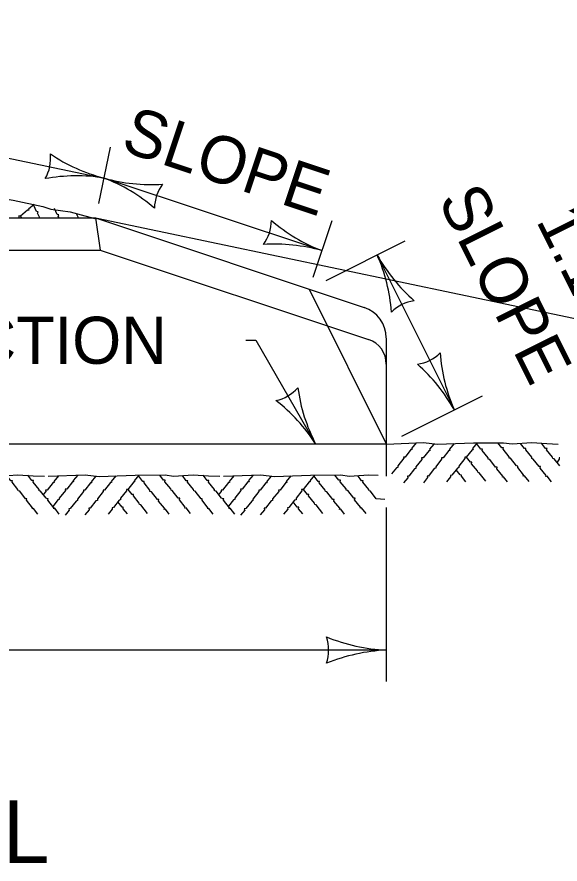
# Model space of a CAD drawing. Extents: x 49991.4 to 50021, y 49987.6 to 50011.4.
# Drawn here: x 50014.7 to 50015.391, y 49996.72 to 49997.798 of the extents above; entities that cross this region are included whole.
import ezdxf

# ---------------------------------------------------------------- set-up
doc = ezdxf.new("R2010")
doc.units = 0
for name, color, linetype in [('Level 1', 7, 'Continuous'), ('Level 2', 7, 'Continuous'), ('Level 3', 7, 'Continuous'), ('Level 4', 7, 'Continuous')]:
    doc.layers.add(name, color=color, linetype=linetype)

msp = doc.modelspace()

# ---------------------------------------------------------------- linework, layer by layer
at = {"layer": 'Level 1'}
for p, q in [((50012.6493, 49997.5423), (50014.7997, 49997.5423)), ((50014.7997, 49997.5423), (50015.1415, 49997.4284)), ((50015.1696, 49997.3894), (50015.1696, 49997.2136))]:
    msp.add_line(p, q, dxfattribs=at)
for points in [[(50014.5862, 49997.5861), (50014.6327, 49997.5783), (50014.6498, 49997.5726), (50014.6948, 49997.5648), (50014.7326, 49997.557), (50014.7427, 49997.5534), (50014.7674, 49997.5501), (50014.786, 49997.5449), (50014.8003, 49997.5411)], [(50014.7215, 49997.5594), (50014.7143, 49997.5536), (50014.7146, 49997.5521), (50014.7131, 49997.5524), (50014.704, 49997.5446), (50014.7022, 49997.545), (50014.7019, 49997.5423)], [(50014.7289, 49997.5423), (50014.7257, 49997.5486), (50014.7264, 49997.5503), (50014.7246, 49997.5506), (50014.721, 49997.5581)], [(50014.7532, 49997.5423), (50014.752, 49997.5446), (50014.7527, 49997.5464), (50014.7509, 49997.5467), (50014.7473, 49997.5542)], [(50014.7054, 49997.5423), (50014.7044, 49997.5444)], [(50014.7779, 49997.5423), (50014.7755, 49997.5476)], [(50015.1698, 49997.2545), (50015.217, 49997.2564), (50015.2349, 49997.2545), (50015.2805, 49997.256), (50015.3189, 49997.2562), (50015.3296, 49997.2548), (50015.3546, 49997.2564), (50015.3738, 49997.2554), (50015.3885, 49997.2545)], [(50015.2078, 49997.2562), (50015.2018, 49997.249), (50015.2025, 49997.2474), (50015.201, 49997.2474), (50015.1936, 49997.238), (50015.1916, 49997.238), (50015.192, 49997.2364), (50015.1842, 49997.2268), (50015.1842, 49997.2248), (50015.1826, 49997.2244), (50015.1764, 49997.2164)], [(50015.2302, 49997.2544), (50015.2247, 49997.2478), (50015.2256, 49997.2462), (50015.2241, 49997.2462), (50015.2166, 49997.2368), (50015.2146, 49997.2368), (50015.2148, 49997.235), (50015.2072, 49997.2254), (50015.2072, 49997.2234), (50015.2056, 49997.223), (50015.1982, 49997.2134), (50015.1965, 49997.2134), (50015.1968, 49997.2114), (50015.1916, 49997.2052)], [(50015.2559, 49997.2552), (50015.2499, 49997.2479), (50015.2506, 49997.2464), (50015.2492, 49997.2464), (50015.2418, 49997.237), (50015.2397, 49997.237), (50015.24, 49997.2352), (50015.2325, 49997.2256), (50015.2325, 49997.2239), (50015.2307, 49997.2232), (50015.2235, 49997.2138), (50015.2216, 49997.2136), (50015.222, 49997.2119), (50015.2168, 49997.2053)], [(50015.2853, 49997.256), (50015.2793, 49997.2488), (50015.28, 49997.2473), (50015.2787, 49997.2473), (50015.2712, 49997.238), (50015.2694, 49997.238), (50015.2696, 49997.236), (50015.2619, 49997.2264), (50015.2619, 49997.2248), (50015.2602, 49997.224), (50015.2529, 49997.2148), (50015.2512, 49997.2144), (50015.2514, 49997.2128), (50015.2463, 49997.2064)], [(50015.3237, 49997.2064), (50015.3189, 49997.2126), (50015.3174, 49997.2124), (50015.3177, 49997.2138), (50015.3102, 49997.223), (50015.3106, 49997.225), (50015.3087, 49997.225), (50015.3012, 49997.2348), (50015.2994, 49997.2352), (50015.2992, 49997.2368), (50015.2918, 49997.2462), (50015.2919, 49997.2479), (50015.2901, 49997.248), (50015.285, 49997.2546)], [(50015.3512, 49997.2068), (50015.3456, 49997.2142), (50015.3438, 49997.2138), (50015.3442, 49997.2154), (50015.3368, 49997.2246), (50015.337, 49997.2264), (50015.3354, 49997.2268), (50015.3278, 49997.2364), (50015.3261, 49997.2366), (50015.3258, 49997.2384), (50015.3182, 49997.2478), (50015.3186, 49997.2496), (50015.3166, 49997.2496), (50015.3116, 49997.2562)], [(50015.3798, 49997.2064), (50015.3742, 49997.2134), (50015.3728, 49997.2132), (50015.373, 49997.2144), (50015.3656, 49997.2239), (50015.366, 49997.2258), (50015.364, 49997.226), (50015.3566, 49997.2354), (50015.3548, 49997.2359), (50015.3546, 49997.2378), (50015.3471, 49997.247), (50015.3472, 49997.2488), (50015.3456, 49997.2488), (50015.3405, 49997.2554)], [(50015.3903, 49997.2268), (50015.3832, 49997.2358), (50015.3816, 49997.236), (50015.3813, 49997.2378), (50015.3736, 49997.2472), (50015.3741, 49997.249), (50015.3722, 49997.249), (50015.3669, 49997.2558)], [(50015.2962, 49997.2072), (50015.2876, 49997.218), (50015.2859, 49997.2185), (50015.2858, 49997.2203), (50015.2782, 49997.2294), (50015.2784, 49997.2314), (50015.2766, 49997.2314), (50015.2716, 49997.2378)], [(50015.3906, 49997.237), (50015.3896, 49997.237), (50015.3897, 49997.2352), (50015.387, 49997.2316)], [(50015.2706, 49997.2066), (50015.2652, 49997.2134), (50015.2655, 49997.215), (50015.2636, 49997.2154), (50015.2586, 49997.2218)], [(50014.5163, 49997.2135), (50014.5634, 49997.2154), (50014.5813, 49997.2133), (50014.6267, 49997.2148), (50014.6653, 49997.2151), (50014.6759, 49997.2136), (50014.7008, 49997.2154), (50014.7201, 49997.2142), (50014.7347, 49997.2135)], [(50014.7263, 49997.1651), (50014.7207, 49997.1725), (50014.7193, 49997.1721), (50014.7195, 49997.1734), (50014.7119, 49997.183), (50014.7123, 49997.1847), (50014.7105, 49997.1849), (50014.7031, 49997.1945), (50014.7013, 49997.195), (50014.7009, 49997.1967), (50014.6935, 49997.2059), (50014.6939, 49997.2076), (50014.6919, 49997.2076), (50014.6867, 49997.2145)], [(50014.7368, 49997.1855), (50014.7297, 49997.1945), (50014.7279, 49997.1951), (50014.7278, 49997.1968), (50014.7201, 49997.2059), (50014.7205, 49997.2079), (50014.7187, 49997.2079), (50014.7134, 49997.2148)], [(50014.7524, 49997.2141), (50014.7464, 49997.207), (50014.7471, 49997.2055), (50014.7457, 49997.2055), (50014.7381, 49997.1959), (50014.7373, 49997.1959)], [(50014.7393, 49997.2135), (50014.7865, 49997.2154), (50014.8043, 49997.2133), (50014.8499, 49997.2148), (50014.8883, 49997.2151), (50014.8989, 49997.2136), (50014.9239, 49997.2154), (50014.9432, 49997.2142), (50014.9579, 49997.2135)], [(50014.7769, 49997.2149), (50014.7711, 49997.2079), (50014.7717, 49997.2065), (50014.7704, 49997.2065), (50014.7629, 49997.1969), (50014.7609, 49997.1969), (50014.7613, 49997.1953), (50014.7535, 49997.1855), (50014.7535, 49997.1839), (50014.7518, 49997.1833), (50014.7458, 49997.1755)], [(50014.7997, 49997.2133), (50014.7939, 49997.2065), (50014.7947, 49997.2052), (50014.7932, 49997.2052), (50014.7859, 49997.1956), (50014.7841, 49997.1956), (50014.7842, 49997.1939), (50014.7765, 49997.1842), (50014.7765, 49997.1825), (50014.7749, 49997.1818), (50014.7675, 49997.1725), (50014.7657, 49997.1722), (50014.7661, 49997.1705), (50014.7608, 49997.1639)], [(50014.8253, 49997.2141), (50014.8193, 49997.207), (50014.8201, 49997.2055), (50014.8185, 49997.2055), (50014.8111, 49997.1959), (50014.8093, 49997.1959), (50014.8094, 49997.1941), (50014.8019, 49997.1847), (50014.8019, 49997.1827), (50014.7999, 49997.1821), (50014.7929, 49997.1727), (50014.7909, 49997.1727), (50014.7914, 49997.1707), (50014.7861, 49997.1644)], [(50014.8547, 49997.2149), (50014.8489, 49997.2076), (50014.8497, 49997.2064), (50014.8483, 49997.2064), (50014.8407, 49997.1968), (50014.8388, 49997.1968), (50014.8389, 49997.1951), (50014.8313, 49997.1855), (50014.8313, 49997.1836), (50014.8298, 49997.1831), (50014.8225, 49997.1737), (50014.8207, 49997.1735), (50014.8209, 49997.1716), (50014.8157, 49997.1653)], [(50014.8934, 49997.1653), (50014.8885, 49997.1716), (50014.8869, 49997.1713), (50014.8873, 49997.1727), (50014.8797, 49997.1819), (50014.8802, 49997.1839), (50014.8784, 49997.1841), (50014.8707, 49997.1937), (50014.8689, 49997.1941), (50014.8688, 49997.1959), (50014.8613, 49997.2051), (50014.8615, 49997.207), (50014.8597, 49997.207), (50014.8545, 49997.2135)], [(50014.9205, 49997.1659), (50014.9151, 49997.1731), (50014.9133, 49997.1728), (50014.9138, 49997.1741), (50014.9063, 49997.1835), (50014.9067, 49997.1854), (50014.9048, 49997.1855), (50014.8973, 49997.1953), (50014.8957, 49997.1956), (50014.8953, 49997.1974), (50014.8877, 49997.2065), (50014.8881, 49997.2085), (50014.8862, 49997.2085), (50014.8813, 49997.2149)], [(50014.9493, 49997.1651), (50014.9439, 49997.1725), (50014.9425, 49997.1721), (50014.9427, 49997.1734), (50014.9353, 49997.183), (50014.9355, 49997.1847), (50014.9339, 49997.1849), (50014.9263, 49997.1945), (50014.9245, 49997.195), (50014.9241, 49997.1967), (50014.9167, 49997.2059), (50014.9169, 49997.2076), (50014.9151, 49997.2076), (50014.9101, 49997.2145)], [(50014.9599, 49997.1855), (50014.9529, 49997.1945), (50014.9511, 49997.1951), (50014.9509, 49997.1968), (50014.9433, 49997.2059), (50014.9437, 49997.2079), (50014.9417, 49997.2079), (50014.9365, 49997.2148)], [(50014.9755, 49997.2141), (50014.9695, 49997.207), (50014.9702, 49997.2055), (50014.9687, 49997.2055), (50014.9613, 49997.1959), (50014.9605, 49997.1959)], [(50014.9625, 49997.2135), (50015.0098, 49997.2154), (50015.0273, 49997.2133), (50015.0733, 49997.2148), (50015.1117, 49997.2151), (50015.1223, 49997.2136), (50015.1472, 49997.2154), (50015.1591, 49997.2147)], [(50015.0002, 49997.2149), (50014.9942, 49997.2079), (50014.9949, 49997.2065), (50014.9935, 49997.2065), (50014.9863, 49997.1969), (50014.9841, 49997.1969), (50014.9845, 49997.1953), (50014.9768, 49997.1855), (50014.9768, 49997.1839), (50014.9751, 49997.1833), (50014.9689, 49997.1755)], [(50015.0227, 49997.2133), (50015.0173, 49997.2065), (50015.0179, 49997.2052), (50015.0165, 49997.2052), (50015.0091, 49997.1956), (50015.0073, 49997.1956), (50015.0074, 49997.1939), (50014.9997, 49997.1842), (50014.9997, 49997.1825), (50014.9983, 49997.1818), (50014.9907, 49997.1725), (50014.9889, 49997.1722), (50014.9894, 49997.1705), (50014.9841, 49997.1639)], [(50015.0483, 49997.2141), (50015.0423, 49997.207), (50015.0433, 49997.2055), (50015.0417, 49997.2055), (50015.0344, 49997.1959), (50015.0325, 49997.1959), (50015.0327, 49997.1941), (50015.0249, 49997.1847), (50015.0249, 49997.1827), (50015.0233, 49997.1821), (50015.0159, 49997.1727), (50015.0141, 49997.1727), (50015.0145, 49997.1707), (50015.0092, 49997.1644)], [(50015.0781, 49997.2149), (50015.0721, 49997.2076), (50015.0728, 49997.2064), (50015.0713, 49997.2064), (50015.0639, 49997.1968), (50015.0619, 49997.1968), (50015.0623, 49997.1951), (50015.0547, 49997.1855), (50015.0547, 49997.1836), (50015.0529, 49997.1831), (50015.0457, 49997.1737), (50015.0437, 49997.1735), (50015.0441, 49997.1716), (50015.0389, 49997.1653)], [(50015.1165, 49997.1653), (50015.1118, 49997.1716), (50015.1101, 49997.1713), (50015.1105, 49997.1727), (50015.1029, 49997.1819), (50015.1034, 49997.1839), (50015.1015, 49997.1841), (50015.0939, 49997.1937), (50015.0923, 49997.1941), (50015.0919, 49997.1959), (50015.0843, 49997.2051), (50015.0848, 49997.207), (50015.0829, 49997.207), (50015.0779, 49997.2135)], [(50015.1439, 49997.1659), (50015.1382, 49997.1731), (50015.1367, 49997.1728), (50015.1369, 49997.1741), (50015.1293, 49997.1835), (50015.1299, 49997.1854), (50015.1281, 49997.1855), (50015.1207, 49997.1953), (50015.1187, 49997.1956), (50015.1185, 49997.1974), (50015.1111, 49997.2065), (50015.1112, 49997.2085), (50015.1094, 49997.2085), (50015.1043, 49997.2149)], [(50015.1679, 49997.1838), (50015.1569, 49997.1849), (50015.1495, 49997.1945), (50015.1477, 49997.195), (50015.1473, 49997.1967), (50015.1399, 49997.2059), (50015.1401, 49997.2076), (50015.1382, 49997.2076), (50015.1333, 49997.2145)], [(50014.7369, 49997.1959), (50014.7361, 49997.1959), (50014.7362, 49997.1941), (50014.7333, 49997.1907)], [(50014.8658, 49997.1661), (50014.8573, 49997.1771), (50014.8555, 49997.1775), (50014.8551, 49997.1791), (50014.8477, 49997.1884), (50014.8479, 49997.1902), (50014.8461, 49997.1902), (50014.8411, 49997.1968)], [(50014.9601, 49997.1959), (50014.9594, 49997.1959), (50014.9595, 49997.1941), (50014.9567, 49997.1907)], [(50015.0889, 49997.1661), (50015.0803, 49997.1771), (50015.0787, 49997.1775), (50015.0783, 49997.1791), (50015.0707, 49997.1884), (50015.0711, 49997.1902), (50015.0692, 49997.1902), (50015.0643, 49997.1968)], [(50014.7533, 49997.1653), (50014.7479, 49997.1727), (50014.7464, 49997.1722), (50014.7465, 49997.1735), (50014.7391, 49997.183), (50014.7393, 49997.1848), (50014.7377, 49997.1849), (50014.7373, 49997.1855)], [(50014.9767, 49997.1653), (50014.9709, 49997.1727), (50014.9695, 49997.1722), (50014.9699, 49997.1735), (50014.9624, 49997.183), (50014.9627, 49997.1848), (50014.9609, 49997.1849), (50014.9605, 49997.1855)], [(50014.8401, 49997.1656), (50014.8347, 49997.1722), (50014.8349, 49997.1741), (50014.8333, 49997.1741), (50014.8279, 49997.1809)], [(50015.0632, 49997.1656), (50015.0578, 49997.1722), (50015.0583, 49997.1741), (50015.0563, 49997.1741), (50015.0511, 49997.1809)]]:
    msp.add_lwpolyline(points, dxfattribs=at)
msp.add_arc((50015.1284, 49997.3895), 0.0411, 0, 71.5416, dxfattribs=at)
at = {"layer": 'Level 3'}
for p, q in [((50013.8318, 49997.7982), (50014.8104, 49997.5931)), ((50014.8036, 49997.5609), (50014.8187, 49997.6323)), ((50015.0876, 49997.5007), (50014.8104, 49997.5931)), ((50015.1003, 49997.5387), (50015.0762, 49997.4664)), ((50015.0931, 49997.4628), (50015.1938, 49997.513)), ((50015.158, 49997.4951), (50015.2562, 49997.2979)), ((50014.9909, 49997.3866), (50015.0034, 49997.3866)), ((50015.0034, 49997.3866), (50015.0797, 49997.2547)), ((50015.1893, 49997.2646), (50015.292, 49997.3157)), ((50015.1696, 49997.1736), (50015.1696, 49996.9522)), ((50015.1696, 49996.9922), (50014.4064, 49996.9922))]:
    msp.add_line(p, q, dxfattribs=at)
for centre, radius, start, end in [((50014.6899, 49997.6184), 0.0526, 330.3022, 6.0246), ((50014.8627, 49997.8), 0.2134, 235.6194, 255.8029), ((50014.7754, 49997.3722), 0.2237, 80.9907, 100.2406), ((50014.7346, 49997.3936), 0.2134, 49.0092, 69.1927), ((50014.8706, 49997.8085), 0.2237, 254.3805, 273.6303), ((50014.9272, 49997.5542), 0.0526, 143.692, 179.4143), ((50014.9709, 49997.5397), 0.0526, 323.692, 359.4143), ((50015.1635, 49997.7002), 0.2134, 229.0092, 249.1927), ((50015.0274, 49997.2853), 0.2237, 74.3805, 93.6303), ((50014.9632, 49997.408), 0.2134, 3.9205, 24.104), ((50015.3531, 49997.6046), 0.2237, 209.2918, 228.5417), ((50015.2129, 49997.3849), 0.0526, 98.6033, 134.3257), ((50015.2013, 49997.4081), 0.0526, 278.6033, 314.3257), ((50015.451, 49997.3851), 0.2134, 183.9205, 204.104), ((50015.0611, 49997.1885), 0.2237, 29.2918, 48.5417), ((50015.0181, 49997.3613), 0.0526, 282.1701, 317.8924), ((50015.2687, 49997.3538), 0.2134, 187.4873, 207.6708), ((50014.8918, 49997.1333), 0.2237, 32.8586, 52.1084), ((50015.1788, 49997.2143), 0.2223, 247.456, 267.6395), ((50015.0414, 49996.9922), 0.0548, 342.1388, 17.8612), ((50015.1811, 49996.7595), 0.233, 92.8273, 112.0772)]:
    msp.add_arc(centre, radius, start, end, dxfattribs=at)
at = {"layer": 'Level 4'}
for p, q in [((50014.7997, 49997.5423), (50014.8057, 49997.5013)), ((50014.8017, 49997.542), (50016.1675, 49997.2547)), ((50012.6493, 49997.5013), (50014.8057, 49997.5013)), ((50014.8057, 49997.5013), (50015.147, 49997.3875)), ((50015.0713, 49997.4518), (50015.1696, 49997.2547)), ((50012.6493, 49997.2547), (50015.1696, 49997.2547))]:
    msp.add_line(p, q, dxfattribs=at)
msp.add_arc((50015.1367, 49997.3563), 0.0329, 0, 71.5749, dxfattribs=at)

# ---------------------------------------------------------------- texts
at = {"layer": 'Level 2'}
for s, rotation, p in [('SLOPE', 341.5752, (50014.83, 49997.6287)), ('SLOPE', 296.4886, (50015.2347, 49997.5654)), ('1:1', 296.4886, (50015.3595, 49997.5391))]:
    msp.add_text(s, height=0.06, rotation=rotation, dxfattribs=at).set_placement(p)
for s, height, p in [('END SECTION', 0.06, (50014.3419, 49997.3566)), ('SLOPE DETAIL', 0.08, (50013.9799, 49996.721))]:
    msp.add_text(s, height=height, dxfattribs=at).set_placement(p)

doc.saveas('drawing.dxf')
